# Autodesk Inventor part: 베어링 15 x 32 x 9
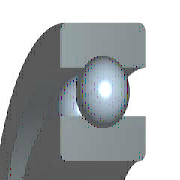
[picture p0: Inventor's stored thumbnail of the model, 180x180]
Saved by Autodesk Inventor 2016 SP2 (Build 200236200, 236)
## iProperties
IsCustomPart: 0
Created: 2012-02
Part Number: 베어링 15 x 32 x 9
Material: 강철, 연강
Description: 깊은 그루브 볼 베어링
Document SubType Name: Modeling
Standard: KS B 2023
Designer: mduedu
Standards Organization: KS
Language: ko-KR
Size Designation: 6002 - 15 x 32 x 9
Categories: <MemberInstance><Categories><Category DisplayName="샤프트 부품" InternalName="7f7aeb1f-a693-4053-b835-cee3144e0d98" Mnemonic="SHFT"><Category DisplayName="베어링" Inter
Density: 1 g/cm^3
Appearance: 노란색
Author: mduedu
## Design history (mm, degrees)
sketch "스케치" dims "d0" = 4.42 (= -0.26 x WD + 0.26 x BD)
  geometry: L1 (2.29, 11.75)-(6.71, 11.75); L2 (4.5, 11.75)-(4.5, 9.54); L3 (4.5, 11.75)-(4.5, 13.96); L4 (2.858, 10.271)-(0, 10.271); L5 (0, 7.5)-(9, 7.5); L6 (2.858, 13.229)-(0, 13.229); L7 (0, 16)-(9, 16); L8 (9, 7.5)-(9, 10.271); L9 (6.142, 10.271)-(9, 10.271); L10 (6.142, 13.229)-(9, 13.229); L11 (9, 16)-(9, 13.229); L12 (-1.4, 0)-(8.4, 0) reference; L13 (0, -0.3)-(0, 5.3) reference
  constraints: 22 end point, 4 point on line, 2 collinear, 2 perpendicular, 2 symmetric about line, 1 midpoint, 1 parallel, 14 other
  dimensions: "d9" = 15 diameter of L5 L12 (= WD); "d11" = 32 diameter of L7 L12 (= BD); "d12" = 9 distance between parallel lines of L8 L13 (= KB); "d13" = 20.542 diameter of L9 L12 (= 0.326 x BD + 0.674 x WD)
revolve "본체" stored, may be unused: angle "d6" = 90 deg
revolve "볼" stored, may be unused: angle "d7" = 90 deg
pattern_circular "IDS_ARRAYBALL[SIMPL:T]" dims angle "d3" = 360 deg
body "Solid1"
fillet "모깎기1" dims "d1" = 0.3 (= KRS)
other parameters: "WD" = 15 [user parameter; used in 5 equation terms], "BD" = 32 [user parameter; used in 5 equation terms], "KB" = 9 [user parameter; used in 1 equation term], "KRS" = 0.3 [user parameter; used in 1 equation term], "d4" = 0, "d5" = 0, "d8" = 0, "d14" = 0, "d15" = 0, "BBA" = 0 [user parameter], "BC0" = 2850000 [user parameter], "BC" = 5590000 [user parameter], "BR" = 16 (= 0.5 x BD) [user parameter], "WR" = 7.5 (= 0.5 x WD) [user parameter]
